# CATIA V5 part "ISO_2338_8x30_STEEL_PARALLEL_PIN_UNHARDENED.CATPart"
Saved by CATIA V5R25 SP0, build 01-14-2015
Part number: ISO 2338 PIN 8x30 STEEL PARALLEL UNHARDENED
Publications: "Mating Edge", "Axis"
Bounding box of the stored display mesh (mm): x 0 to 30, y -4 to 4, z -3.804 to 3.804
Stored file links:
  D:\feridun18052022montaj\ISO_2338_8x30_STEEL_PARALLEL_PIN_UNHARDENED.CATPart
  C:\Program Files\Dassault Systemes\B25\win_b64\startup\components\MechanicalStandardParts\ISO_Standards\Design_Tables\ISO_2338_PARALLEL_PIN.txt
  D:\feridun18052022montaj\cektirme.CATProduct
  D:\feridun18052022montaj\03.CATPart
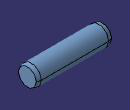
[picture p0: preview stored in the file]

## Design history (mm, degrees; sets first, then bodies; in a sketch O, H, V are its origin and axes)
Parameters
  d_dia = 8 mm
  c = 1.6 mm
  l_length_nom = 30 mm
Body1 "PartBody" (main body)
  Sketch1 on yz-plane, origin (0, 0, 0), H (0, 1, 0), V (0, 0, 1)
    circle A1 centre (0, 0) radius 4
    radius A1 = 4 {= d_dia /2}
  Pad1: profile Sketch1, direction (1, 0, 0), length 30 {= l_length_nom}
  Chamfer1: length 1.6 {= c}, angle 15, on edge [face of Pad1 | face of Pad1]
  Chamfer2: length 1.6 {= c}, angle 15, on edge [face of Pad1 | face of Pad1]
